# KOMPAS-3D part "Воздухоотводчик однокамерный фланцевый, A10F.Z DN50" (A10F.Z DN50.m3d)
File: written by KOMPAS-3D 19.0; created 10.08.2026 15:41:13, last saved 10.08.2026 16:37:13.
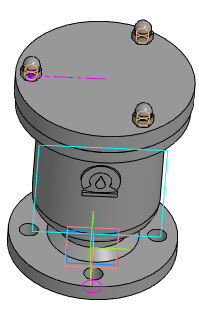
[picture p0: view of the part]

Document properties: Автор: Энергия; Полное имя файла: Z:\3.Личные\kachalov\001_3d для проектировщиков\x.x Тип A10F.Z Воздухоотводчик однокамерный фланцевый\A10F.Z DN50.m3d

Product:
- Part/product: Воздухоотводчик однокамерный фланцевый  | designation A10F.Z DN50
    Масса: 19.654
  - Component [standard]: Гайка М12-6H (S18) ГОСТ 11860-85  | qty 3  | Масса: 0.02606; Раздел спецификации: Стандартные изделия; Рассекать на разрезах: no; source file: C:\Program Files\ASCON\KOMPAS-3D v19\Libs\PARTLib\DATA\vault\Methods\Kompas\3D\PLib_Blind_Nut_type1_900.m3d

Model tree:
1. Эскиз:1
2. Элемент вращения:1
     Угол 1 = 360
3. Скругление:1  (with: Элемент вращения:1)
     Радиус = 10
4. Фаска:1  (with: Элемент вращения:1)
     Угол = 45; Длина 1 = 10; Длина 2 = 10
5. Эскиз:2  (with: Элемент вращения:1)
6. Точка:1
     Y = -72.5; Z = 213; Координата Y = -72.5; Координата Z = 213
7. Массив по концентрической сетке:1  (with: Элемент вращения:1)  (3 pattern instances)
     Шаг 2 = 360
8. Эскиз:3  (with: Элемент вращения:1)
9. Элемент выдавливания:1  (with: Элемент вращения:1, Массив по концентрической сетке:1, Эскиз:3)  (4 pattern instances)
     Расстояние 2 = 16; N 1 = 1; Шаг 1 = 10; Шаг 2 = 360; Номер 1 = 1
10. Касательная плоскость:1  (with: Элемент вращения:1)
11. Эскиз:4
12. Элемент выдавливания:2  (with: Элемент вращения:1)  (labels: Фаска наружная:1)
     Расстояние 1 = 1; Ориентация = 2

Expressions: Dn/2; D2/2; D/2; B/2; D1/2; D1+20; H/2
Referenced files in C:\Program Files\ASCON\KOMPAS-3D v19\Libs\PARTLib\DATA\vault\Methods\Kompas\3D\: PLib_Blind_Nut_type1_900.m3d
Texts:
  A10F.Z DN50
  Гайка М12-6H (S18) ГОСТ 11860-85 (1)
  foc1
  foc2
